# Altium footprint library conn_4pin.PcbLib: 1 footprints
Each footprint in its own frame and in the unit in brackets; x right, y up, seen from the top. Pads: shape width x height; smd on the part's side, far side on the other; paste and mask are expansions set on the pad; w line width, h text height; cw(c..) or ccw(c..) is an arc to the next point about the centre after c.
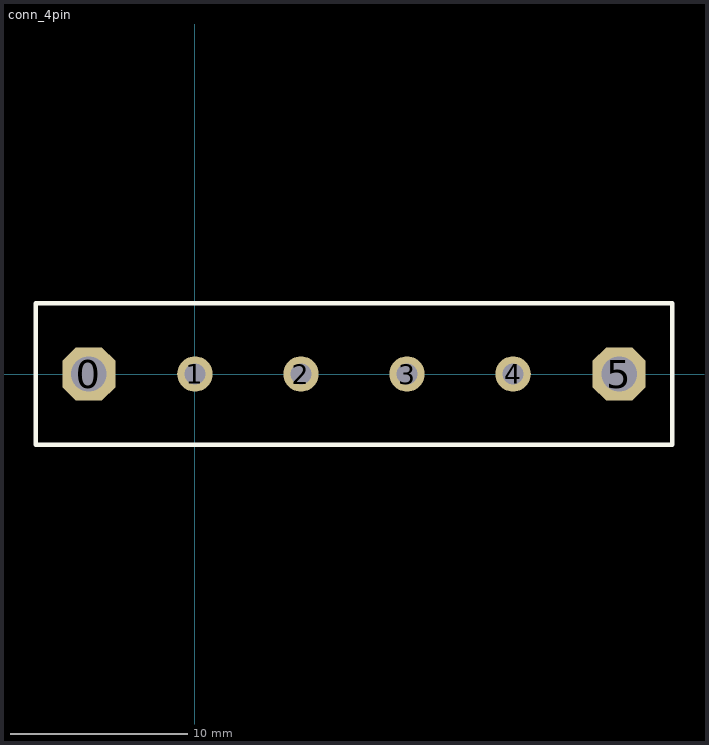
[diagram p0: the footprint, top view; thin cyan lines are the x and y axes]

## conn_4pin [mm]
pads (6):
  oct 3x3 hole 2: 0(-6,0) 5(24,0)
  round 2 hole 1.2: 1(0,0) 2(6,0) 3(12,0) 4(18,0)
Top Overlay:
  lines w0.254: -9,-4 27,-4 27,4 -9,4 -9,-4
